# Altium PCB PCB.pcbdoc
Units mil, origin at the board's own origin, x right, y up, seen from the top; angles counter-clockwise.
Board outline 2605 x 3140 mil, 4 copper layers (Top Layer, Inner1, VCC, Bottom Layer); 72 components, 50 nets, 258 pads, 167 vias.
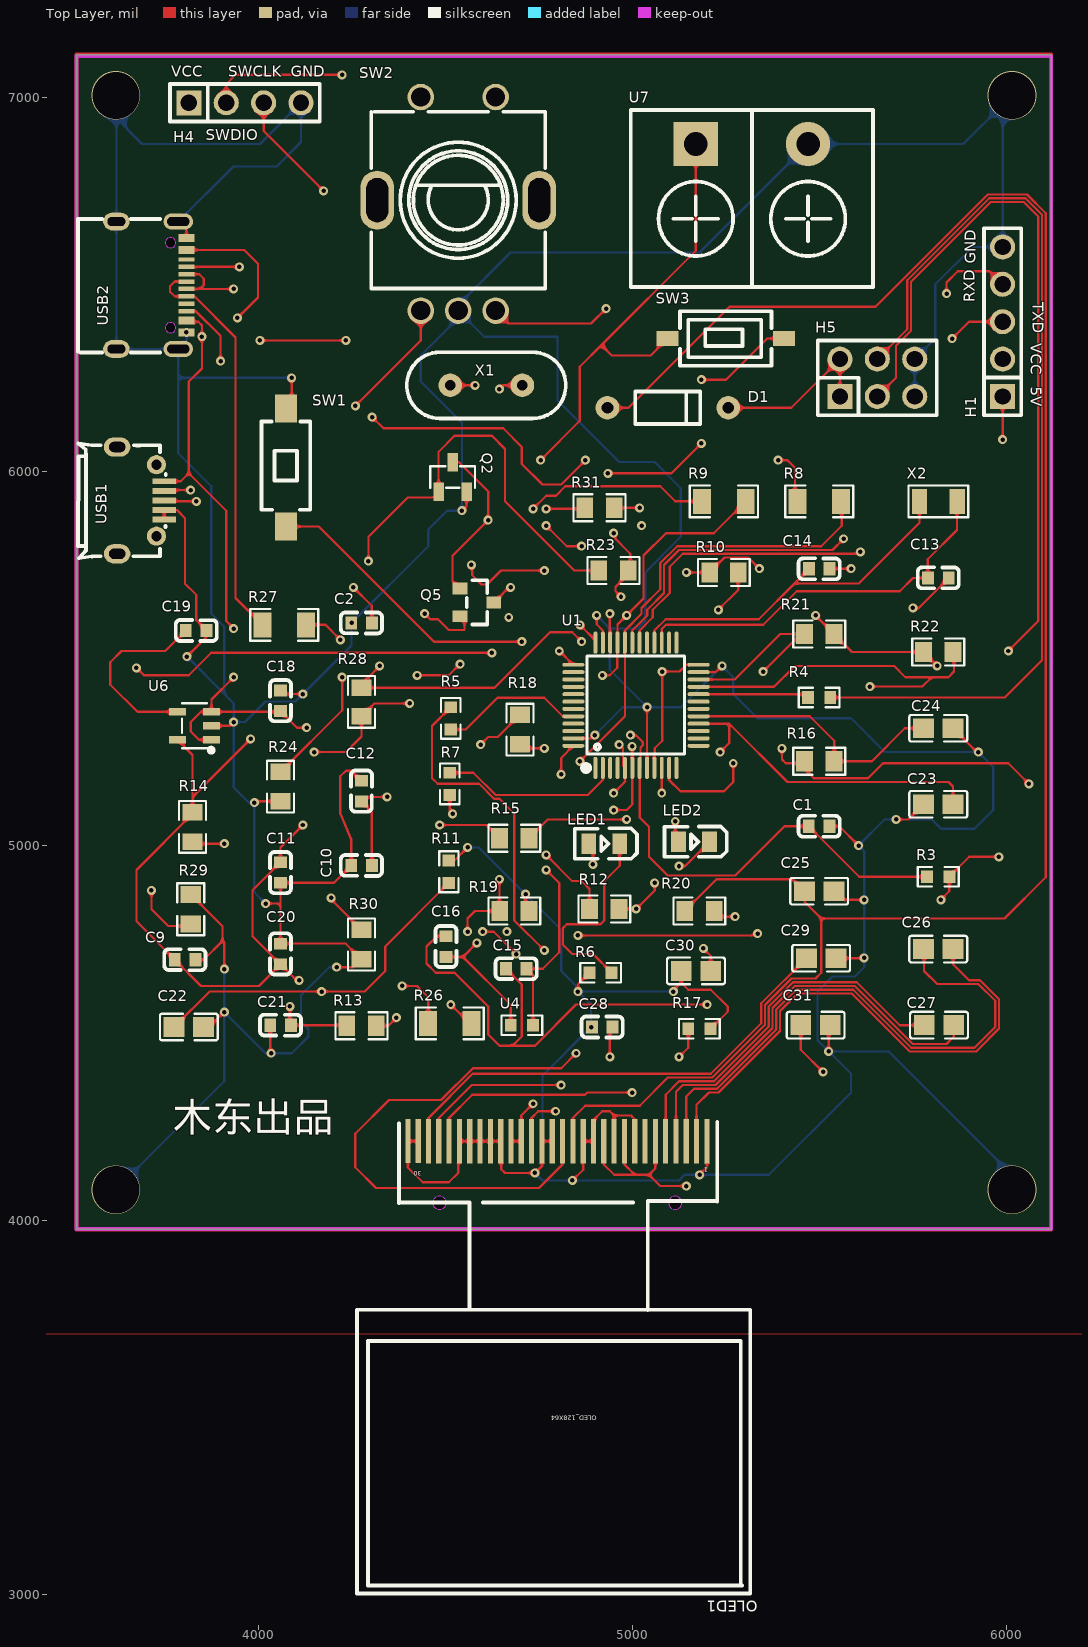
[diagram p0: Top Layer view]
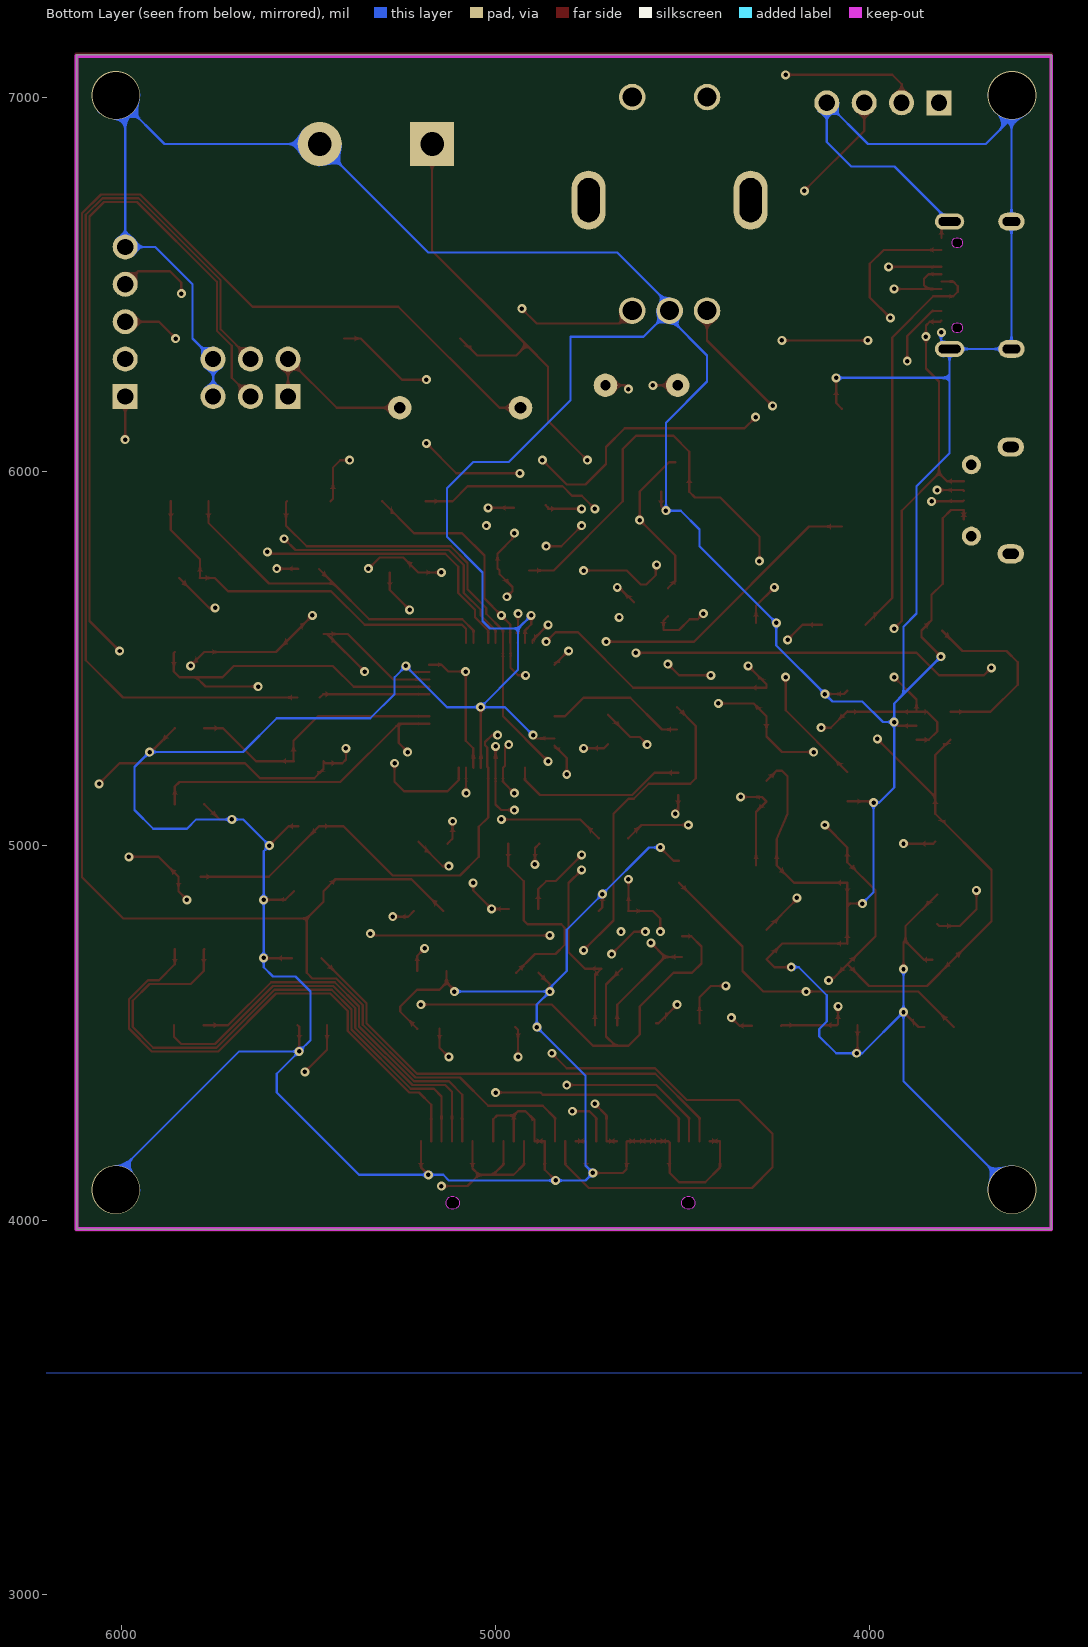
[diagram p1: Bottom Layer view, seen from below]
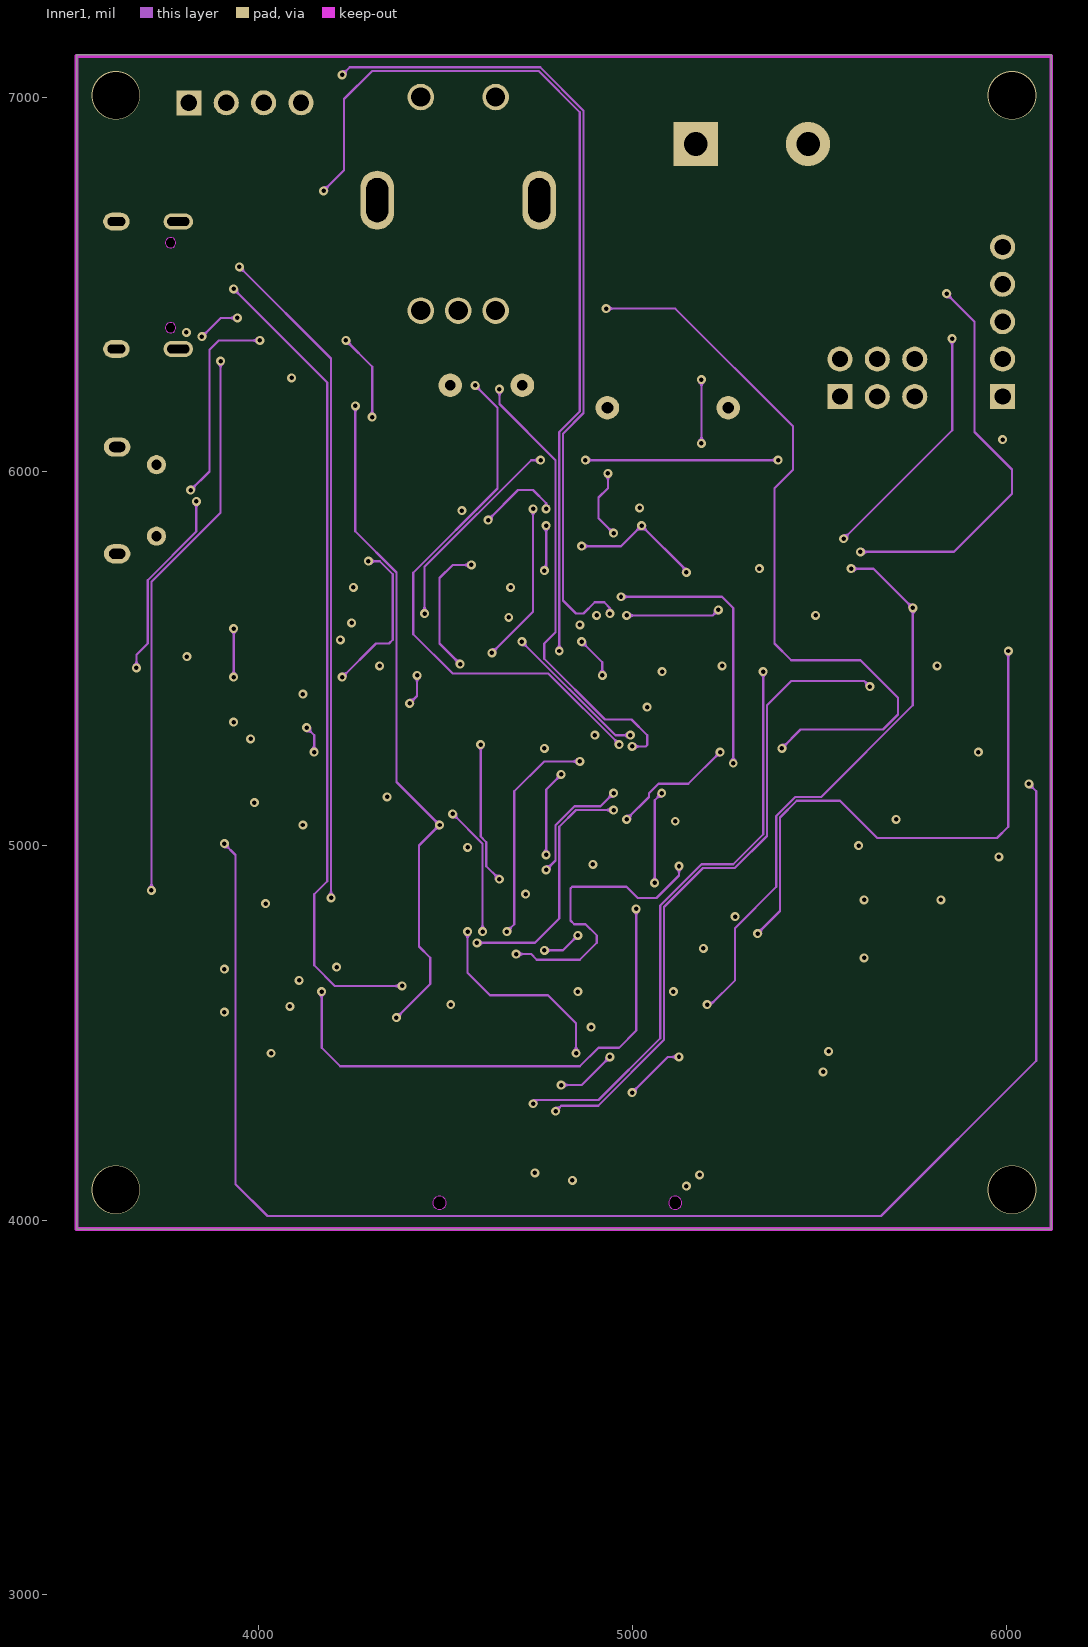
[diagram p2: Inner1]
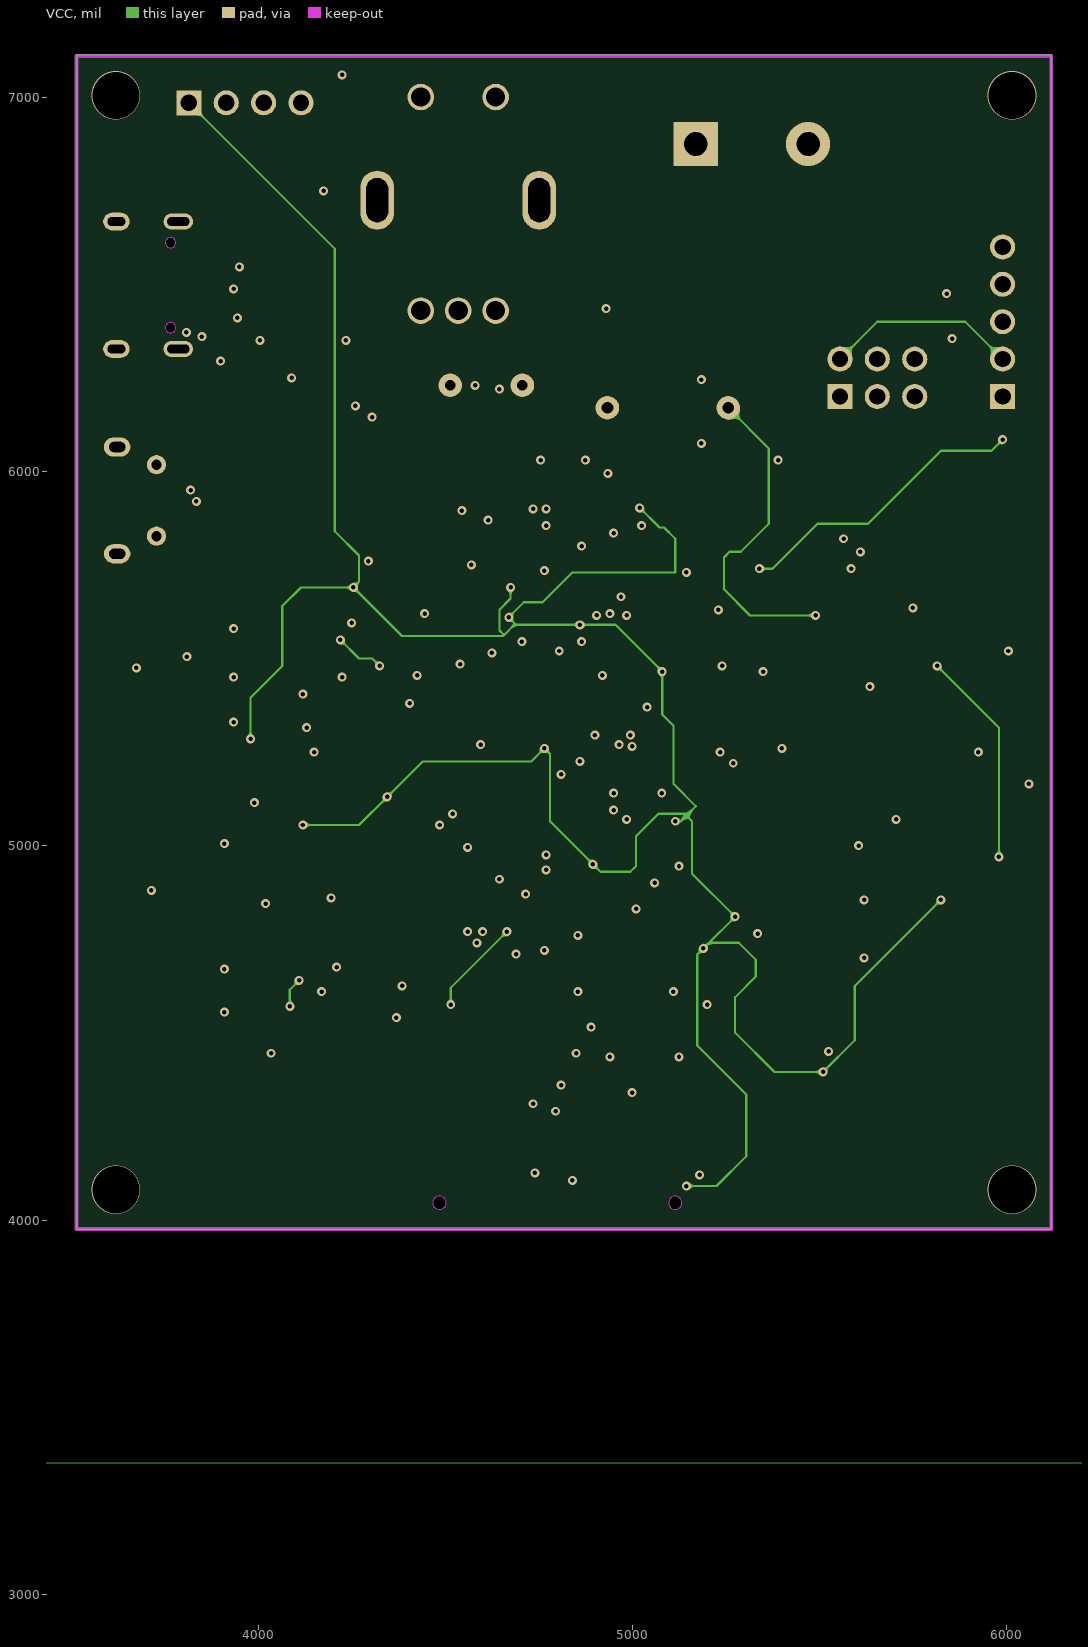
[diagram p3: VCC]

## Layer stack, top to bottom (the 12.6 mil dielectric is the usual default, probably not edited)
Top Solder Mask Layer: solder mask 0.4, Solder Resist, Dk 3.5
Top Layer: signal copper 1.4
Dielectric1: dielectric 12.6, FR-4, Dk 4.8
Inner1: signal copper 1.4
Dielectric2: dielectric 12.6, FR-4, Dk 4.8
VCC: signal copper 1.4
Dielectric3: dielectric 12.6, FR-4, Dk 4.8
Bottom Layer: signal copper 1.4
Bottom Solder Mask Layer: solder mask 0.4, Solder Resist, Dk 3.5

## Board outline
3515,3975 3515,7115 6120,7115 6120,3975

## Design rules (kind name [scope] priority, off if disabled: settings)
Clearance [All] p1: gap=10 ignorepadtopadclearanceinfootprint=FALSE except(0: Arc-Hole Track-Hole SMDPad-Hole THPad-Hole Via-Hole Fill-Hole Poly-Hole Region-Hole Text-Hole)
PolygonConnect [All] p1: connectstyle=Relief reliefconductorwidth=10 reliefentries=4 polygonreliefangle="90 Angle" airgapwidth=10
RoutingVias [All] p1: holewidth=28 width=50 viastyle="Through Hole" minholewidth=28 minwidth=50 maxholewidth=28 maxwidth=50
SolderMaskExpansion [All] p1: expansion=4 istentingtop=FALSE
Width [All] p1: maxlimit=10 minlimit=10 preferedwidth=10
30 further rules are at their usual default settings.

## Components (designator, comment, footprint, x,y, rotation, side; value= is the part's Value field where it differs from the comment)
C1 "0603B104K500NT" C0603 5499.37,5052.67 r180 top
C2 "0603B104K500NT" C0603 4276.64,5596.02 r0 top
C9 "0603B104K500NT" C0603 3805,4696.02 r0 top
C10 "0603B104K500NT" C0603 4276.64,4947.8 r0 top
C11 "0603B104K500NT" C0603 4060.11,4929.18 r90 top
C12 "0603B104K500NT" C0603 4276.23,5146.48 r270 top
C13 "0603CG200J500NT" C0603 5818.23,5716.38 r0 top
C14 "0603CG200J500NT" C0603 5499.98,5740.5 r0 top
C15 "0603CG200J500NT" C0603 4690.21,4672.01 r0 top
C16 "0603CG200J500NT" C0603 4502.2,4731.02 r270 top
C18 "CL10A105KB8NNNC" C0603 4059.89,5387.9 r270 top
C19 "0603B223K500NT" C0603 3834.59,5575.82 r180 top
C20 "0603B104K500NT" C0603 4059.89,4711.21 r270 top
C21 "CL10A106KP8NNNC" C0603 4060.3,4521.02 r0 top
C22 "0805B104K500NT" C0805 3815,4516.02 r180 top
C23 "0805B103K500NT_C52278" C0805 5817.92,5111.41 r0 top
C24 "0805B103K500NT_C52278" C0805 5817.92,5314.59 r0 top
C25 "GRM21BR61H106KE43L" C0805 5499.67,4879.06 r0 top
C26 "CL21B105KBFNNNE" C0805 5817.92,4724.2 r0 top
C27 "CL21B105KBFNNNE" C0805 5820,4521.02 r0 top
C28 "CL10A475KO8NNNC" C0603 4920,4516.02 r0 top
C29 "CL21A225KBQNNNE" C0805 5505,4700.04 r0 top
C30 "CL21B105KBFNNNE" C0805 5170.42,4666.08 r0 top
C31 "CL21B105KBFNNNE" C0805 5490,4521.02 r180 top
D1 "1N4148_C402212" DO-35_BD2.0-L4.2-P8.20-D0.5-RD 5095,6171.02 r180 top
H1 "PZ254V-11-05P" HDR-TH_5P-P2.54-V-M 5990,6401.02 r90 top
H4 "PZ254V-11-04P" HDR-TH_4P-P2.54-V-M 3965,6986.02 r0 top
H5 "PZ254V-12-6P" HDR-TH_6P-P2.54-V-M-R2-C3-S2.54 5655,6251.02 r0 top
LED1 "NCD0805R1" LED0805-R-RD 4925,5006.02 r180 top
LED2 "NCD0805R1" LED0805-R-RD 5165,5011.02 r180 top
OLED1 "N096-2864KSWEG01-H30" OLED_0.96-30P-P0.70-12864 4800,4211.02 r180 top
Q2 "SS8050_C2150" SOT-23-3_L2.9-W1.3-P1.90-LS2.4-BR 4520,5986.02 r270 top
Q5 "AO3400_C2938367" SOT-23_L2.9-W1.3-P1.90-LS2.4-BR 4585,5651.02 r180 top
R3 "0603WAF1002T5E" R0603 5817.92,4917.81 r0 top
R4 "RC0603FR-07100KL" R0603 5499.67,5396.59 r180 top
R5 "RC0603FR-07100KL" R0603 4515,5341.02 r90 top
R6 "0603WAF5100T5E" R0603 4915.42,4660.87 r180 top
R7 "0603WAF5100T5E" R0603 4512.31,5166.02 r90 top
R8 "1206W4F200JT5E" R1206 5499.67,5921.02 r0 top
R9 "1206W4F200JT5E" R1206 5245,5921.02 r0 top
R10 "0805W8F100JT5E" R0805_NEW 5245,5731.02 r0 top
R11 "NCP18XH103F03RB" R0603 4510,4931.02 r90 top
R12 "0805W8F1002T5E_C17414" R0805 4925.42,4831.65 r180 top
R13 "0805W8F1002T5E_C17414" R0805 4276.33,4519.49 r0 top
R14 "0805W8F1002T5E_C17414" R0805 3825,5051.02 r90 top
R15 "0805W8F1002T5E_C17414" R0805 4684.9,5020.55 r0 top
R16 "0805W8F1002T5E_C17414" R0805 5499.67,5226.6 r0 top
R17 "0603WAF9103T5E" R0603 5179.55,4511.45 r180 top
R18 "0805W8F4701T5E" R0805 4699.9,5311.02 r90 top
R19 "0805W8F4701T5E" R0805 4685,4826.02 r180 top
R20 "0805W8F4701T5E" R0805 5179.55,4826.02 r0 top
R21 "0805W8F4701T5E" R0805 5499.67,5566.57 r180 top
R22 "0805W8F4701T5E" R0805 5817.92,5518.3 r0 top
R23 "0805W8F1001T5E" R0805 4950,5736.02 r0 top
R24 "0805W8F1003T5E" R0805 4060,5158.54 r90 top
R26 "1206W4F200JT5E" R1206 4512.31,4526.02 r0 top
R27 "1206W4F200JT5E" R1206 4070,5591.02 r0 top
R28 "0805W8F100JT5E" R0805_NEW 4276.33,5384.94 r90 top
R29 "0805W8F5101T5E" R0805 3820,4831.02 r90 top
R30 "0805W8F5101T5E" R0805 4276.33,4736.72 r90 top
R31 "0805W8F1003T5E" R0805 4912.45,5903.66 r0 top
SW1 "TS-1101-C-W" SW-SMD_L6.0-W3.3-LS8.0 4075,6011.02 r270 top
SW2 "EC11E15244G1" SW-TH_EC11E15244G1 4535,6716.02 r0 top
SW3 "TS-1092S-B3D2-G" SW-SMD_L6.1-W3.6-LS7.9 5250,6356.02 r0 top
U1 "STM32F103C8T6" LQFP-48_L7.0-W7.0-P0.50-LS9.0-BL 5010,5376.02 r0 top
U4 "SC0603F1004F2BNRH" R0603 4705,4521.02 r0 top
U6 "RT9193-33GB" SOT-23-5_L3.0-W1.7-P0.95-LS2.8-BL 3830,5321.02 r90 top
U7 "KF7.62-2P" CONN-TH_KF7.62-2P 5320,6876.02 r0 top
USB1 "MicroXNJ" MICRO-USB-SMD_MICROXNJ 3686.26,5923.48 r270 top
USB2 "TYPE-C 16PIN 2MD(073)" USB-C-SMD_TYPE-C-6PIN-2MD-073 3715,6498.48 r270 top
X1 "X49SD8MSD2SC" OSC-TH_L10.0-W4.5-P5.00 4610,6231.02 r90 top
X2 "X321532768KGD2SI" OSC-SMD_L3.2-W1.5 5817.92,5921.04 r0 top

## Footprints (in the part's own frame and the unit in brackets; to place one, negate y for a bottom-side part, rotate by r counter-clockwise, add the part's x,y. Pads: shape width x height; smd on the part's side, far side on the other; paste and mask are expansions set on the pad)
C0603 [mm]
  rect 0.8x0.9 smd: 1(-0.7,0) 2(0.7,0)
  silkscreen extent -1.41,-0.71 1.39,0.72
C0805 [mm]
  rect 1.41x1.35 smd paste-100 mask+0.051: 1(-1,0) 2(1,0)
  silkscreen extent -1.96,-0.9 1.96,0.9
CONN-TH_KF7.62-2P [mm]
  rect 3x3 hole 1.6: 1(-3.81,0)
  round 3 hole 1.6: 2(3.81,0)
  silkscreen extent -8.22,-9.7 8.22,2.3
DO-35_BD2.0-L4.2-P8.20-D0.5-RD [mm]
  round 1.6 hole 0.8: 1(-4.1,0) 2(4.1,0)
  silkscreen extent -2.2,-1.1 2.2,1.1
HDR-TH_4P-P2.54-V-M [mm]
  rect 1.7x1.7 hole 1.1: 1(-3.81,0)
  round 1.7 hole 1.1: 2(-1.27,0) 3(1.27,0) 4(3.81,0)
  silkscreen extent -5.08,-1.27 5.08,1.27
HDR-TH_5P-P2.54-V-M [mm]
  rect 1.7x1.7 hole 1.1: 1(-5.08,0)
  round 1.7 hole 1.1: 2(-2.54,0) 3(0,0) 4(2.54,0) 5(5.08,0)
  silkscreen extent -6.35,-1.27 6.35,1.27
HDR-TH_6P-P2.54-V-M-R2-C3-S2.54 [mm]
  rect 1.7x1.7 hole 1.1: 1(-2.54,-1.27)
  round 1.7 hole 1.1: 2(-2.54,1.27) 3(0,-1.27) 4(0,1.27) 5(2.54,-1.27) 6(2.54,1.27)
  silkscreen extent -4.04,-2.54 4.04,2.54
LED0805-R-RD [mm]
  rect 1x1.4 smd: 1(1.05,0) 2(-1.05,0)
  silkscreen extent -2.22,-1.04 1.99,1.01
LQFP-48_L7.0-W7.0-P0.50-LS9.0-BL [mm]
  oval 0.27x1.5 smd paste+0 mask+0.05: 1(-2.75,-4.25) 2(-2.25,-4.25) 3(-1.75,-4.25) 4(-1.25,-4.25) 5(-0.75,-4.25) 6(-0.25,-4.25) 7(0.25,-4.25) 8(0.75,-4.25) 9(1.25,-4.25) 10(1.75,-4.25) 11(2.25,-4.25) 12(2.75,-4.25) 25(2.75,4.25) 26(2.25,4.25) 27(1.75,4.25) 28(1.25,4.25) 29(0.75,4.25) 30(0.25,4.25) 31(-0.25,4.25) 32(-0.75,4.25) 33(-1.25,4.25) 34(-1.75,4.25) 35(-2.25,4.25) 36(-2.75,4.25)
  oval 1.5x0.27 smd paste+0 mask+0.05: 13(4.25,-2.75) 14(4.25,-2.25) 15(4.25,-1.75) 16(4.25,-1.25) 17(4.25,-0.75) 18(4.25,-0.25) 19(4.25,0.25) 20(4.25,0.75) 21(4.25,1.25) 22(4.25,1.75) 23(4.25,2.25) 24(4.25,2.75) 37(-4.25,2.75) 38(-4.25,2.25) 39(-4.25,1.75) 40(-4.25,1.25) 41(-4.25,0.75) 42(-4.25,0.25) 43(-4.25,-0.25) 44(-4.25,-0.75) 45(-4.25,-1.25) 46(-4.25,-1.75) 47(-4.25,-2.25) 48(-4.25,-2.75)
  silkscreen extent -3.59,-4.46 3.3,3.34
MICRO-USB-SMD_MICROXNJ [mm]
  rect 0.4x1.6 smd paste-100 mask+0.051: 1(-1.3,1.596) 2(-0.65,1.596) 3(0,1.596) 4(0.65,1.596) 5(1.3,1.596)
  round 1.3 hole 0.7: 6(2.425,1.074) 9(-2.425,1.074)
  oval 1.3x1.8 hole 0.7 slot 1.1 at 90 deg: 7(3.625,-1.596) 8(-3.625,-1.596)
  silkscreen extent -3.87,-4.24 3.93,1.71
OLED_0.96-30P-P0.70-12864 [mm]
  rect 0.351x3 smd: 1(-10.15,0.002) 2(-9.45,0) 3(-8.75,0) 4(-8.05,0) 5(-7.35,0) 6(-6.65,0) 7(-5.95,0) 8(-5.25,0) 9(-4.55,0) 10(-3.85,0) 11(-3.15,0) 12(-2.45,0) 13(-1.75,0) 14(-1.05,0) 15(-0.35,0) 16(0.35,0) 17(1.05,0) 18(1.75,0) 19(2.45,0) 20(3.15,0) 21(3.85,0) 22(4.55,0) 23(5.25,0) 24(5.95,0) 25(6.65,0) 26(7.35,0) 27(8.05,0) 28(8.75,-0.001) 29(9.45,-0.002) 30(10.15,-0.002)
  Board Outline Layer board cut-out: -8.45,4.18 -8.45,4.091 -8.381,3.925 -8.255,3.799 -8.089,3.73 -7.91,3.73 -7.745,3.799 -7.618,3.925 -7.55,4.091 -7.55,4.18 -7.55,4.27 -7.618,4.435 -7.745,4.562 -7.91,4.63 -8.089,4.63 -8.255,4.562 -8.381,4.435 -8.45,4.27 -8.45,4.18
  Board Outline Layer board cut-out: 7.55,4.18 7.55,4.091 7.618,3.925 7.745,3.799 7.911,3.73 8.09,3.73 8.255,3.799 8.382,3.925 8.45,4.091 8.45,4.18 8.45,4.27 8.382,4.435 8.255,4.562 8.09,4.63 7.91,4.63 7.745,4.562 7.618,4.435 7.55,4.27 7.55,4.18
  Multi-Layer keep-out region: -8.45,4.18 -8.45,4.091 -8.381,3.925 -8.255,3.799 -8.089,3.73 -7.91,3.73 -7.745,3.799 -7.618,3.925 -7.55,4.091 -7.55,4.18 -7.55,4.27 -7.618,4.435 -7.745,4.562 -7.91,4.63 -8.089,4.63 -8.255,4.562 -8.381,4.435 -8.45,4.27 -8.45,4.18
  Multi-Layer keep-out region: 7.55,4.18 7.55,4.091 7.618,3.925 7.745,3.799 7.911,3.73 8.09,3.73 8.255,3.799 8.382,3.925 8.45,4.091 8.45,4.18 8.45,4.27 8.382,4.435 8.255,4.562 8.09,4.63 7.91,4.63 7.745,4.562 7.618,4.435 7.55,4.27 7.55,4.18
  silkscreen extent -13.1,-1.3 13.6,30.7
OSC-SMD_L3.2-W1.5 [mm]
  rect 1.05x1.7 smd: 1(-1.275,0) 2(1.275,0)
  silkscreen extent -2.03,-1.08 2.03,1.08
OSC-TH_L10.0-W4.5-P5.00 [mm]
  round 1.6 hole 0.7: 1(0,2.45) 2(0,-2.45)
  silkscreen extent -2.25,-5.39 2.25,5.39
R0603 [mil]
  rect 31.75x34.02 smd paste-3937.01 mask+2: 1(-29.66,0) 2(29.66,0)
  silkscreen extent -55,-26 55,26
R0805 [mm]
  rect 1.133x1.377 smd paste-100 mask+0.051: 1(-1,0) 2(1,0)
  silkscreen extent -1.76,-0.92 1.76,0.92
R0805_NEW [mil]
  rect 44.59x54.21 smd paste-3937.01 mask+2: 1(-38.04,0) 2(38.04,0)
  silkscreen extent -69,-36 69,36
R1206 [mil]
  rect 47.54x66.97 smd paste-3937.01 mask+2: 1(-58.22,0) 2(58.22,0)
  silkscreen extent -91,-42 91,42
SOT-23-3_L2.9-W1.3-P1.90-LS2.4-BR [mm]
  rect 1.25x0.7 smd: 1(1,-0.95) 2(1,0.95) 3(-1,0)
  silkscreen extent -0.73,-1.53 0.73,1.53
SOT-23-5_L3.0-W1.7-P0.95-LS2.8-BL [mm]
  rect 0.49x1.157 smd: 1(-0.95,-1.154) 2(0,-1.154) 3(0.95,-1.154)
  rect 0.49x1.175 smd: 4(0.95,1.154) 5(-0.95,1.154)
  silkscreen extent -1.8,-1.29 1.53,0.85
SOT-23_L2.9-W1.3-P1.90-LS2.4-BR [mm]
  rect 1x0.8 smd: 1(1.15,-0.95) 2(1.15,0.95) 3(-1.15,0)
  silkscreen extent -0.7,-1.5 0.7,1.5
SW-SMD_L6.0-W3.3-LS8.0 [mm]
  rect 1.9x1.5 smd: 1(-4,0) 2(4,0)
  silkscreen extent -3.14,-1.67 2.86,1.63
SW-SMD_L6.1-W3.6-LS7.9 [mm]
  rect 1.5x1 smd: 1(-3.95,0) 2(3.95,0)
  silkscreen extent -3.1,-1.85 3.1,1.85
SW-TH_EC11E15244G1 [mm]
  oval 2.3x4 hole 1.5 slot 3 at 90 deg: 6(5.5,0.25) 7(-5.5,0.25)
  round 1.8 hole 1.3: A(-2.54,-7.25) B(2.54,-7.25) C(0,-7.25) D(-2.54,7.25) E(2.54,7.25)
  silkscreen extent -5.9,-5.75 5.9,6.25
USB-C-SMD_TYPE-C-6PIN-2MD-073 [mm]
  rect 0.55x1.1 smd paste-100 mask+0.05: 1(-3.2,2.375) 2(-2.4,2.375) 11(2.4,2.375) 12(3.2,2.375)
  rect 0.3x1.1 smd paste-100 mask+0.05: 3(-1.75,2.375) 4(-1.25,2.375) 5(-0.75,2.375) 6(-0.25,2.375) 7(0.25,2.375) 8(0.75,2.375) 9(1.25,2.375) 10(1.75,2.375)
  oval 1.1x2 hole 0.6 slot 1.5 at 90 deg paste+0 mask+0.05: 13(-4.325,1.825) 14(4.325,1.825)
  oval 1.2x1.8 hole 0.6 slot 1.2 at 90 deg paste+0 mask+0.05: 13(-4.325,-2.375) 14(4.325,-2.375)
  Board Outline Layer board cut-out: -2.89,1.655 -2.96,1.655 -3.088,1.602 -3.187,1.503 -3.24,1.375 -3.24,1.235 -3.187,1.107 -3.088,1.008 -2.959,0.955 -2.89,0.955 -2.82,0.955 -2.692,1.008 -2.593,1.107 -2.54,1.235 -2.54,1.375 -2.593,1.503 -2.692,1.602 -2.82,1.655 -2.89,1.655
  Board Outline Layer board cut-out: 2.89,1.655 2.821,1.655 2.692,1.602 2.593,1.503 2.54,1.375 2.54,1.235 2.593,1.107 2.692,1.008 2.821,0.955 2.89,0.955 2.96,0.955 3.088,1.008 3.187,1.107 3.24,1.235 3.24,1.375 3.187,1.503 3.088,1.602 2.96,1.655 2.89,1.655
  Multi-Layer keep-out region: -2.89,1.655 -2.96,1.655 -3.088,1.602 -3.187,1.503 -3.24,1.375 -3.24,1.235 -3.187,1.107 -3.088,1.008 -2.959,0.955 -2.89,0.955 -2.82,0.955 -2.692,1.008 -2.593,1.107 -2.54,1.235 -2.54,1.375 -2.593,1.503 -2.692,1.602 -2.82,1.655 -2.89,1.655
  Multi-Layer keep-out region: 2.89,1.655 2.821,1.655 2.692,1.602 2.593,1.503 2.54,1.375 2.54,1.235 2.593,1.107 2.692,1.008 2.821,0.955 2.89,0.955 2.96,0.955 3.088,1.008 3.187,1.107 3.24,1.235 3.24,1.375 3.187,1.503 3.088,1.602 2.96,1.655 2.89,1.655
  silkscreen extent -4.5,-4.97 4.57,0.6

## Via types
v1: diameter 24, hole 12, Top Layer to Bottom Layer, 163 vias
v2: diameter 130, hole 126, Top Layer to Bottom Layer, 4 vias

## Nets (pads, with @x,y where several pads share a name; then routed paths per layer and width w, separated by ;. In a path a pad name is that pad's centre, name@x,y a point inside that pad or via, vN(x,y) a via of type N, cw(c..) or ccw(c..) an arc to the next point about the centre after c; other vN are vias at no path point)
$1N1632: H5.3 R5.2 | length 4926.9
  Top Layer w6: R5.2 4465,5320.68 4465,5181.02 4480,5166.02 4590.84,5166.02 4630.85,5126.01 4645.02,5126.01 4685,5086.02 4685,4801.02 v1(4765,4721.02) ; v1(4855,4761.02) 5330,4761.02 v1(5335,4766.02) ; H5.3 5705,6251.02 5705,6336.86 5745.02,6376.87 5745.02,6507.71 5958.3,6720.99 6046.7,6720.99 6085.16,6682.53 6085.16,5601.18 v1(6005,5521.02)
  Inner1 w6: v1(4765,4721.02) 4815,4721.02 v1(4855,4761.02) ; v1(5335,4766.02) 5395,4826.02 5395,5076.02 5440,5121.02 5555,5121.02 5655,5021.02 5975,5021.02 6005,5051.02 v1(6005,5521.02)
$1N1633: H5.4 R4.1 | length 2511
  Top Layer w6: R4.1 5995.74,5396.59 6095.17,5496.02 6095.17,6686.68 6050.85,6731.01 5954.15,6731.01 5735,6511.86 5735,6381.02 H5.4
$1N1645: LED1.2 R6.1 | length 546.6
  Top Layer w6: R6.1 4894.93,4711.02 4840,4711.02 4815.02,4736.01 4815.02,4781.04 4825,4791.02 4915,4791.02 4925,4801.02 4925,4906.02 4966.35,4947.37 LED1.2
$1N1649: LED2.2 R7.1 | length 1410.6
  Top Layer w6: R7.1 4512.31,5093.71 v1(4520,5086.02) ; v1(4600,4771.02) 4630,4771.02 v1(4690,4711.02) ; v1(5125,4946.02) 5141.35,4946.02 LED2.2
  Inner1 w6: v1(4520,5086.02) 4600,5006.02 v1(4600,4771.02) ; v1(4690,4711.02) 4730,4711.02 4745,4696.02 4860,4696.02 4905,4741.02 4905,4761.02 4875,4791.02 4845,4791.02 4835,4801.02 4835,4886.02 4840,4891.02 4985,4891.02 5015,4861.02 5065,4861.02 5125,4921.02 v1(5125,4946.02)
$1N1662: R8.1 USB1.2 | length 2435.6
  Top Layer w6: USB1.2 3751.07,5951.02 v1(3820,5951.02) ; v1(4005,6351.02) v1(4235,6351.02) ; v1(4305,6146.02) 4335,6116.02 4655,6116.02 4705,6066.02 4705,6021.02 4760,5966.02 4810,5966.02 v1(4875,6031.02) ; v1(5390,6031.02) 5415,6031.02 5435,6011.02 5435,5927.47 R8.1
  Inner1 w6: v1(3820,5951.02) 3870,6001.02 3870,6326.02 3895,6351.02 v1(4005,6351.02) ; v1(4235,6351.02) 4305,6281.02 v1(4305,6146.02) ; v1(4875,6031.02) v1(5390,6031.02)
$1N1663: R9.1 USB1.3 | length 2505.1
  Top Layer w6: v1(3675,5476.02) 3695,5456.02 3815,5456.02 3875,5516.02 v1(4625,5516.02) ; USB1.3 3751.56,5921.02 v1(3835,5921.02) ; v1(4735,5901.02) 4770,5936.02 4796,5936.02 4821,5961.02 5075,5961.02 5115,5921.02 R9.1
  Inner1 w6: v1(3675,5476.02) 3675,5511.04 3704.98,5541.02 3704.98,5710.17 3835,5840.19 v1(3835,5921.02) ; v1(4625,5516.02) 4735,5626.02 v1(4735,5901.02)
$1N1675: C13.2 C14.2 C15.1 C16.1 | length 3002.6
  Top Layer w6: C16.1 4477.56,4758.58 4450,4731.02 4450,4686.02 4475,4661.02 4525,4661.02 4615,4571.02 4615,4496.02 4645,4466.02 4680,4466.02 ; C15.1 4705,4629.66 4705,4491.02 4680,4466.02 ; v1(5200,4576.02) 4850,4576.02 4740,4466.02 4680,4466.02 ; C14.2 5528.06,5741.02 v1(5585,5741.02) ; v1(5750,5636.02) 5765.43,5636.02 C13.2
  Inner1 w6: v1(5200,4576.02) 5210,4576.02 5275,4641.02 5275,4781.04 5384.98,4891.02 5384.98,5080.17 5435.85,5131.04 5505.02,5131.04 5750,5376.02 v1(5750,5636.02) 5645,5741.02 v1(5585,5741.02)
$1N1700: C19.2 U6.4 | length 506.8
  Top Layer w6: U6.4 3677.6,5358.42 3605,5431.02 3605,5491.02 3635,5521.02 3752.23,5521.02 C19.2
$1N6862: R13.2 R15.1 SW2.A | length 2366.2
  Top Layer w6: v1(4260,6176.02) 4434.99,6351.02 SW2.A ; R13.2 4348.47,4519.49 v1(4370,4541.02) ; v1(4485,5056.02) 4610.06,5056.02 R15.1
  Inner1 w6: v1(4260,6176.02) 4260,5841.02 4370,5731.02 4370,5171.02 v1(4485,5056.02) 4430,5001.02 4430,4731.02 4460,4701.02 4460,4631.02 v1(4370,4541.02)
$1N6871: R14.1 R16.1 SW2.B | length 7211.5
  Top Layer w6: R14.1 3830.63,5006.02 v1(3910,5006.02) ; SW2.B 4669.56,6396.02 4890,6396.02 v1(4930,6436.02) ; v1(5400,5261.02) 5400,5231.02 5410,5221.02 5454.72,5221.02 R16.1 5460.3,5205.74 5485,5181.04 5630.02,5181.04 5670,5221.02 6005,5221.02 v1(6060,5166.02)
  Inner1 w6: v1(3910,5006.02) 3940,4976.02 3940,4096.02 4025,4011.02 5665,4011.02 6080,4426.02 6080,5146.02 v1(6060,5166.02) ; v1(4930,6436.02) 5115,6436.02 5430,6121.02 5430,6006.02 5380,5956.02 5380,5541.02 5425,5496.02 5610,5496.02 5710,5396.02 5710,5351.02 5670,5311.02 5450,5311.02 v1(5400,5261.02)
$1N7228: OLED1.26 R17.2 | length 829.7
  Top Layer w6: OLED1.26 4510.63,4273.07 4572.59,4335.02 4874,4335.02 4880,4341.02 v1(5000,4341.02) ; v1(5125,4436.02) 5149.89,4460.91 R17.2
  Inner1 w6: v1(5000,4341.02) 5095,4436.02 v1(5125,4436.02)
$1N7293: OLED1.15 R18.2 R19.2 | length 2695.2
  Top Layer w6: v1(4560,4771.02) 4560,4806.02 4580,4826.02 R19.2 4645,4826.65 v1(4645,4911.02) ; v1(4595,5271.02) 4615,5291.02 4640.53,5291.02 R18.2 ; OLED1.15 4813.78,4148.96 4750.85,4086.02 4315,4086.02 4260,4141.02 4260,4231.02 4350,4321.02 4489.24,4321.02 4574.24,4406.02 4810,4406.02 v1(4850,4446.02)
  Inner1 w6: v1(4560,4771.02) 4560,4661.02 4620,4601.02 4775,4601.02 4850,4526.02 v1(4850,4446.02) ; v1(4595,5271.02) 4595,5025.19 4610.02,5010.17 4610.02,4946.02 v1@4640,4916.04
$1N7764: C25.1 D1.2 OLED1.14 R20.1 | length 5371.9
  Top Layer w6: OLED1.14 4841.34,4273.07 4874.3,4306.02 5020,4306.02 5094.98,4381.01 5214.15,4381.01 5355.02,4521.87 5355.02,4575.26 5425.77,4646.02 5490,4646.02 5505,4661.02 5505,4806.02 ; D1.2 4990,6171.02 5260,6441.02 5650,6441.02 5950,6741.02 6055,6741.02 6105.19,6690.83 6105.19,4916.02 5995.19,4806.02 5505,4806.02 ; R20.1 5225.16,4911.01 5428.36,4911.01 C25.1 5460.3,4850.72 5505,4806.02
$1N8175: C26.1 OLED1.3 | length 1533.4
  Top Layer w6: OLED1.3 5144.49,4330.51 5164.94,4350.96 5226.59,4350.96 5385.06,4509.43 5385.06,4562.82 5438.22,4615.97 5590.88,4615.97 5745.85,4461.01 5914.98,4461.01 5970,4516.02 5970,4586.02 5925,4631.02 5815,4631.02 5780,4666.02 5780,4722.75 C26.1
$1N8179: C26.2 OLED1.2 | length 1429.3
  Top Layer w6: OLED1.2 5172.05,4308.07 5204.92,4340.94 5230.74,4340.94 5395.08,4505.28 5395.08,4558.67 5442.37,4605.96 5586.73,4605.96 5741.7,4450.99 5919.13,4450.99 5980.02,4511.87 5980.02,4590.17 5929.15,4641.04 5900,4641.04 5857.29,4683.75 C26.2
$1N8184: C27.2 OLED1.4 | length 1125.7
  Top Layer w6: OLED1.4 5116.93,4342.95 5134.95,4360.97 ; 5135,4360.97 5222.45,4360.97 5375.05,4513.58 5375.05,4566.97 5434.07,4625.99 5595.03,4625.99 5750,4471.02 5840,4471.02 5859.37,4490.39 C27.2
$1N8191: C27.1 OLED1.5 | length 1019.1
  Top Layer w6: OLED1.5 5089.37,4335.39 5124.97,4370.99 5218.3,4370.99 5365.03,4517.72 5365.03,4571.11 5429.92,4636.01 5600.02,4636.01 5715,4521.02 C27.1
$1N8376: C28.2 OLED1.27 | length 669.6
  Top Layer w6: OLED1.27 4483.07,4273.07 4571.02,4361.02 v1(4810,4361.02) ; v1(4940,4436.02) 4940,4508.46 C28.2
  Inner1 w6: v1(4810,4361.02) 4865,4361.02 v1(4940,4436.02)
$1N8381: C29.1 OLED1.28 | length 1280.3
  Top Layer w6: OLED1.28 4455.51,4273.13 4573.4,4391.02 5210,4391.02 5345,4526.02 5345,4579.41 C29.1
$1N9584: Q2.1 R23.1 R24.2 | length 1838.6
  Top Layer w6: R24.2 4225,5362.91 v1(4225,5451.02) ; v1(4295,5761.02) 4295,5826.02 4400,5931.02 4466.97,5931.02 Q2.1 4482.6,6053.62 4525,6096.02 4625,6096.02 4660,6061.02 4660,5921.02 4845,5736.02 R23.1
  Inner1 w6: v1(4225,5451.02) 4315,5541.02 4350,5541.02 4359.98,5551.01 4359.98,5726.02 4324.98,5761.02 v1(4295,5761.02)
$1N10286: R27.1 USB2.6 USB2.8 | length 1086.9
  Top Layer w6: USB2.6 3777.3,6508.32 3765,6496.02 3765,6481.02 3777.07,6468.95 USB2.8 3830.22,6468.95 3940,6359.17 3940,5662.8 R27.1
$1N10301: R26.1 USB2.5 USB2.7 | length 2545.7
  Top Layer w6: USB2.7 3845,6488.63 ; USB2.5 3843.02,6528 3855,6516.02 3855,6498.63 3845,6488.63 ; v1(3935,6488.63) 3845,6488.63 ; v1(4385,4626.02) 4425,4626.02 4455,4596.02 4455,4526.93 R26.1
  Inner1 w6: v1(3935,6488.63) 4184.98,6238.65 4184.98,4906.01 4150,4871.02 4150,4681.02 4205,4626.02 v1(4385,4626.02)
$1N10500: R29.1 USB2.10 | length 1853.5
  Top Layer w6: v1(3715,4881.02) 3715,4831.02 3760,4786.02 3814.37,4786.02 R29.1 ; USB2.10 3833.16,6429.57 3900,6362.73 v1(3900,6296.02)
  Inner1 w6: v1(3715,4881.02) 3715,5706.02 3900,5891.02 v1(3900,6296.02)
$1N10523: R30.2 USB2.4 | length 2048.3
  Top Layer w6: USB2.4 v1(3950,6547.68) ; v1(4195,4861.02) 4195,4857.42 R30.2
  Inner1 w6: v1(3950,6547.68) 4195,6302.68 v1(4195,4861.02)
$1N12991: Q5.2 SW3.1 U7.1 | length 1943.5
  Top Layer w6: v1(4445,5621.02) 4460,5606.02 4480.94,5606.02 4510,5576.96 4551.62,5576.96 4551.62,5601.72 Q5.2 ; v1(4755,6031.02) 4860,6136.02 4860,6281.02 4917.66,6338.68 ; SW3.1 5049.49,6311.02 4945,6311.02 4917.66,6338.36 4917.66,6338.68 ; U7.1 5170,6591.02 4917.66,6338.68
  Inner1 w6: v1(4445,5621.02) 4445,5746.02 4730,6031.02 v1(4755,6031.02)
$1N13700: Q2.3 Q5.1 R31.1 | length 753.5
  Top Layer w6: Q2.3 4536.78,6025.39 4615,5947.17 v1(4615,5871.02) 4520,5776.02 4520,5708.15 Q5.1 ; v1(4770,5901.02) 4859.99,5901.02 4859.98,5904.73 R31.1@4866,5910.74
  Inner1 w6: v1(4615,5871.02) 4695,5951.02 4735,5951.02 4770,5916.02 v1(4770,5901.02)
+5V: C18.2 H1.1 R10.1 R28.1 U6.1 U6.3 USB1.1 USB2.2 USB2.11 | length 5116.5
  Top Layer w6: USB1.1 3793.63,5974.66 3815,5996.02 ; USB2.11 3811.46,6401.02 3840,6401.02 3850,6391.02 v1(3850,6361.02) 3850,6276.02 3815,6241.02 3815,5996.02 ; USB2.2 3963.06,6592.96 4000,6556.02 4000,6466.02 v1(3945,6411.02) ; U6.1 3842.4,5283.62 3820,5306.02 3820,5331.02 3847.4,5358.42 U6.3 ; v1(3935,5451.02) 3875.42,5391.44 U6.3 ; v1(3935,5581.02) 3915,5601.02 3915,5896.02 3815,5996.02 ; v1(4130,5316.02) 4104.22,5316.02 C18.2 4057.97,5358.42 U6.3 ; v1(4150,5251.02) 4235,5251.02 4276.33,5292.35 R28.1 4310.45,5381.02 v1(4405,5381.02) ; v1(4425,5456.02) 4510,5456.02 v1(4540,5486.02) ; v1(4570,5751.02) 4572.22,5748.81 4572.22,5723.81 4597.22,5698.81 4612.13,5698.81 4649.35,5736.02 v1(4765,5736.02) ; v1(4770,5856.02) 4825,5801.02 v1(4865,5801.02) ; v1(5145,5731.02) R10.1 5246.91,5770.97 5310,5770.97 ; 5310.05,5770.97 v1(5340,5741.02) ; v1(5990,6086.02) H1.1
  Inner1 w6: v1(3850,6361.02) 3900,6411.02 v1(3945,6411.02) ; v1(3935,5451.02) v1(3935,5581.02) ; v1(4130,5316.02) 4150,5296.02 v1(4150,5251.02) ; v1(4405,5381.02) 4425,5401.02 v1(4425,5456.02) ; v1(4540,5486.02) 4485,5541.02 4485,5716.02 4520,5751.02 v1(4570,5751.02) ; v1(4765,5736.02) 4770,5741.02 v1(4770,5856.02) ; v1(4865,5801.02) 4970,5801.02 v1(5025,5856.02) 5145,5736.02 v1(5145,5731.02)
  VCC w6: v1(5340,5741.02) 5375,5741.02 5495,5861.02 5630,5861.02 5825,6056.02 5960,6056.02 v1(5990,6086.02)
ADC: C22.2 R11.1 R12.1 U1.10 | length 2759.4
  Top Layer w6: C22.2 3870.63,4611.02 v1(4170,4611.02) 4285,4611.02 4340,4666.02 4340,4731.36 R11.1 ; R12.1 v1(5010.63,4831.65) 5060,4881.02 v1(5060,4901.02) ; v1(5078.9,5141.02) U1.10
  Inner1 w6: v1(4170,4611.02) 4170,4461.02 4220,4411.02 4860,4411.02 4910,4461.02 4965,4461.02 5010.63,4506.65 v1(5010.63,4831.65) ; v1(5060,4901.02) 5060,5122.12 v1(5078.9,5141.02)
BOOT0: R5.1 U1.44 | length 383.3
  Top Layer w6: R5.1 4555.34,5311.36 4640,5396.02 4765,5396.02 4814.53,5346.49 U1.44
BOOT1: R4.2 U1.20 | length 296.4
  Top Layer w6: U1.20 5461.05,5405.55 R4.2
EC_A: C23.2 R15.2 U1.16 | length 1494.8
  Top Layer w6: R15.2 4774.74,5071.02 v1(4985,5071.02) ; U1.16 5259.21,5326.81 ; v1(5235,5251.02) 5259.21,5275.23 5259.21,5326.81 ; C23.2 5857.29,5158.73 5845,5171.02 5415,5171.02 5259.21,5326.81
  Inner1 w6: v1(4985,5071.02) 5045,5131.02 5045,5141.02 5070,5166.02 5150,5166.02 v1(5235,5251.02)
EC_B: C24.1 R16.2 U1.17 | length 720.6
  Top Layer w6: U1.17 5474.53,5346.49 5540,5281.02 5540,5227.56 R16.2 5640.58,5226.6 5728.57,5314.59 C24.1
GND: C1.1 C2.1 C9.2 C10.1 C11.1 C12.1 C18.1 C19.1 C20.1 C21.1 C22.1 C23.1 C24.2 C25.2 C28.1 C29.2 C30.1 C31.1 H1.5 H4.4 H5.5 H5.6 OLED1.1 OLED1.8 OLED1.10 OLED1.12 OLED1.13 OLED1.16 OLED1.17 OLED1.21 OLED1.22 OLED1.23 OLED1.24 OLED1.25 OLED1.29 OLED1.30 Q2.2 R6.2 R11.2 R17.1 R19.1 R24.1 R29.2 R30.1 SW1.1 SW2.C U1.8 U1.23 U1.35 U1.47 U6.2 U7.2 USB1.4 USB1.5 USB2.1 USB2.12 USB2.13 USB2.14 | length 21780.5
  Top Layer w6: USB1.5 USB1.4 3783.14,5897.89 3805,5876.02 3805,5701.02 3835,5671.02 3835,5602.97 C19.1 3862.15,5558.17 v1(3810,5506.02) ; USB2.13@3786.85,6668.75 3808.5,6647.1 USB2.1 ; R29.2 3905,4785.39 3905,4746.02 ; C9.2 3855,4696.02 3905,4746.02 ; C22.1 3870,4516.02 v1(3910,4556.02) ; U6.2 3925,5321.02 v1(3935,5331.02) ; v1(3910,4671.02) 3910,4741.02 3905,4746.02 ; v1(3990,5116.02) 3993.15,5119.17 R24.1 ; v1(4020,4846.02) 4057.83,4846.02 4060.11,4848.3 ; C21.1 4032.74,4448.28 v1(4035,4446.02) ; C20.1 C20.1@4060.11,4738.99 ; C18.1 4069.34,5406.02 v1(4120,5406.02) ; SW1.1 4090,6183.5 v1(4090,6251.02) ; v1(4210,4676.02) 4255,4676.02 R30.1 4234.7,4738.99 C20.1@4060.11,4738.99 ; C12.1 4249.25,5201.02 4235,5201.02 4220,5186.02 4220,5086.02 4249.08,5016.94 C10.1 4202.9,4901.62 C11.1 4060.11,4848.3 ; OLED1.29 OLED1.30 4400.39,4140.63 4440,4101.02 4510,4101.02 4535,4126.02 4535,4207.82 OLED1.25 OLED1.24 OLED1.23 OLED1.22 OLED1.21 4650,4209.43 4650,4136.02 4660,4126.02 v1(4740,4126.02) 4758.66,4144.68 OLED1.17 OLED1.16 ; R11.2 4524.66,4960.68 v1(4560,4996.02) ; v1(4545,5896.02) 4557.4,5908.42 Q2.2 ; v1(4715,4871.02) 4715,4835.39 R19.1 ; v1(4840,4106.02) 4868.9,4134.92 OLED1.13 OLED1.12 4896.46,4267.48 4920,4291.02 4940,4291.02 4951.57,4279.45 ; U1.47 4891.42,5287.44 v1(4900,5296.02) ; v1(4855,4611.02) 4855,4630.1 R6.2 ; v1(4890,4516.02) C28.1 ; v1(4905,5616.02) 4905,5592.29 4921.42,5575.87 U1.35 ; OLED1.10 4951.57,4279.45 ; OLED1.8 5006.69,4269.33 4996.57,4279.45 4951.57,4279.45 ; U1.8 5039.53,5370.55 v1(5040,5371.02) ; v1(5110,4611.02) 5110,4613.92 5131.05,4634.97 ; C30.1 5131.05,4634.97 ; U1.23 5223.58,5464.6 v1(5240,5481.02) ; v1(5180,4121.02) 5199.61,4140.63 OLED1.1 ; R17.1 5255,4557.24 5255,4571.02 5210,4616.02 5150,4616.02 5131.05,4634.97 ; v1(5525,4451.02) 5525,4516.65 C31.1 ; C1.1 5553.35,5052.67 v1(5605,5001.02) ; C25.2 5562.08,4856.02 v1(5620,4856.02) ; C29.2 5619.02,4700.04 v1(5620,4701.02) ; v1(5705,5071.02) 5738.16,5071.02 C23.1 ; C24.2 5920.86,5251.02 v1(5925,5251.02) ; C20.1@4060.11,4738.99 4060.11,4848.3
  Bottom Layer w6: v2(3620,4081.02) 3910,4371.02 v1(3910,4556.02) ; v2(3620,7006.02) 3621.49,7004.53 v2@3621.49,6944.53 ; USB2.13@3786.85,6668.75 3934.12,6816.02 4050,6816.02 4115,6881.02 H4.4 4005,6876.02 3690,6876.02 v2@3621.49,6944.53 ; v1@3805,6371.02 3810,6366.02 3810,6351.35 USB2.14@3786.85,6328.2 ; v1(3810,5506.02) 3910,5406.02 ; v1(3910,4671.02) v1(3910,4556.02) ; v1(4020,4846.02) 3990,4876.02 v1(3990,5116.02) 3975,5116.02 3935,5156.02 v1(3935,5331.02) ; v1(4090,6251.02) 3786.85,6251.02 ; v1(4210,4676.02) 4190,4676.02 4115,4601.02 4115,4531.02 4135,4511.02 4135,4491.02 4090,4446.02 v1(4035,4446.02) 4020,4446.02 v1(3910,4556.02) ; v1(4560,4996.02) 4590,4996.02 v1(4715,4871.02) 4810,4776.02 4810,4666.02 4855,4621.02 v1(4855,4611.02) ; v1(4900,5296.02) 4975,5371.02 v1(5040,5371.02) ; v1(4905,5616.02) 4940,5581.02 ; v1(5110,4611.02) v1(4855,4611.02) ; H5.5 H5.6 5810,6356.02 5810,6501.02 5910,6601.02 H1.5 v2@5990,6981.02 ; v2(6015,4081.02) 6015,4121.02 5685,4451.02 v1(5525,4451.02) ; v2(6015,7006.02) v2@5990,6981.02 ; v2@3621.49,6944.53 3621.49,6668.75 3621.49,6328.2 USB2.14@3786.85,6328.2 ; 3786.85,6251.02 USB2.14@3786.85,6328.2 ; 3786.85,6251.02 3786.85,6049.17 3875,5961.02 3875,5621.02 3910,5586.02 3910,5406.02 ; 3910,5406.02 3935,5381.02 v1(3935,5331.02) ; v1(3935,5331.02) 3965,5331.02 4020,5386.02 4100,5386.02 v1(4120,5406.02) 4250,5536.02 v1(4250,5596.02) 4455,5801.02 4455,5846.02 4505,5896.02 v1(4545,5896.02) 4545,6131.02 4435,6241.02 4435,6311.02 4534.99,6411.02 SW2.C ; SW2.C 4534.99,6446.02 4675,6586.02 5180,6586.02 U7.2 5885,6876.02 v2@5990,6981.02 ; SW2.C 4604.56,6361.02 4800,6361.02 4800,6191.02 4965,6026.02 5060,6026.02 5130,5956.02 5130,5826.02 5035,5731.02 5035,5601.02 5015,5581.02 4940,5581.02 ; v1(4855,4611.02) 4890,4576.02 v1(4890,4516.02) 4760,4386.02 4760,4146.02 v1(4740,4126.02) 4760,4106.02 v1(4840,4106.02) 5125,4106.02 5140,4121.02 v1(5180,4121.02) 5365,4121.02 5585,4341.02 5585,4391.02 v1(5525,4451.02) ; 4940,5581.02 4940,5471.02 v1(5040,5371.02) ; v1(5040,5371.02) 5130,5371.02 v1(5240,5481.02) 5270,5451.02 5270,5406.02 5335,5341.02 5585,5341.02 5675,5251.02 v1(5925,5251.02) 5965,5211.02 5965,5096.02 5915,5046.02 5825,5046.02 5800,5071.02 v1(5705,5071.02) 5675,5071.02 v1(5605,5001.02) 5620,4986.02 v1(5620,4856.02) v1(5620,4701.02) 5620,4676.02 5595,4651.02 5535,4651.02 5495,4611.02 5495,4481.02 v1(5525,4451.02)
  other v1: 3808.5,6372.49
OSCIN: C15.2 U1.5 U4.2 X1.1 | length 2489.2
  Top Layer w6: X1.1 v1(4580,6231.02) ; U4.2 4734.66,4655.12 C15.2 4760.99,4672.01 4805,4716.02 4805,4901.04 v1(4770,4936.04) ; v1(4950,5141.02) 4980.47,5171.49 U1.5 4975.1,5214.07 4975.1,5260.92 v1(4965,5271.02)
  Inner1 w6: v1(4580,6231.02) 4640,6171.02 4640,5955.19 4415,5730.19 4415,5566.02 4520,5461.02 4775.84,5461.02 4965,5271.86 v1(4965,5271.02) ; v1(4770,4936.04) 4794.98,4961.02 4794.98,5055.17 4845.85,5106.04 4915.02,5106.04 v1(4950,5141.02)
OSCOUT: C16.2 U1.6 U4.1 X1.2 | length 2489
  Top Layer w6: C16.2 4547.44,4703.46 ; v1(4585,4741.02) 4547.44,4703.46 ; v1(4645,6221.02) 4655,6231.02 X1.2 ; U4.1 4675.34,4575.56 4547.44,4703.46 ; v1(4950,5096.02) 4985.16,5096.02 5000.16,5111.02 U1.6 5000.16,5265.86 v1(5000,5266.02)
  Inner1 w6: v1(4585,4741.02) 4740,4741.02 4805,4806.02 4805,5051.02 4850,5096.02 v1(4950,5096.02) ; v1(4645,6221.02) 4645,6181.02 4794.98,6031.04 4794.98,5571.01 4765,5541.02 4765,5500.19 4927.08,5338.1 4997.92,5338.1 5040,5296.02 5040,5270.04 5035.98,5266.02 v1(5000,5266.02)
PA11: R8.2 R26.2 U1.32 | length 2136.1
  Top Layer w6: v1(4515,4576.02) 4565,4526.02 R26.2 ; v1(4860,5226.02) 4980.47,5346.49 U1.32 4980.47,5575.87 5025,5620.4 5025,5636.02 5075,5686.02 5075,5756.02 5120,5801.02 5505,5801.02 5560,5856.02 5560,5918.91 R8.2
  Inner1 w6: v1(4665,4771.02) 4685,4791.02 4685,5146.02 4765,5226.02 v1(4860,5226.02)
  VCC w6: v1(4515,4576.02) 4515,4621.02 v1(4665,4771.02)
PA12: R9.2 R10.2 R27.2 R28.2 U1.33 | length 2177.4
  Top Layer w6: R27.2 4180,5591.02 v1(4220,5551.02) ; v1(4325,5481.02) 4276.33,5432.35 R28.2 4631.96,5422.98 4780,5571.02 4840,5571.02 v1(4865,5546.02) ; v1(4920,5456.02) 4940,5456.02 4960,5476.02 4960,5542.55 U1.33 4960.79,5591.81 v1(4985,5616.02) 5030,5661.02 5030,5776.02 5090,5836.02 5218.22,5836.02 R9.2 ; v1(5230,5631.02) 5283.04,5684.06 R10.2
  Inner1 w6: v1(4865,5546.02) 4920,5491.02 v1(4920,5456.02) ; v1(4985,5616.02) 5215,5616.02 v1(5230,5631.02)
  VCC w6: v1(4220,5551.02) 4270,5501.02 4305,5501.02 v1(4325,5481.02)
PC13: R7.2 U1.2 | length 483
  Top Layer w6: R7.2 4575.34,5195.68 4635,5136.02 4881.27,5136.02 4921.42,5176.17 U1.2
PC14: C13.1 U1.27 X2.2 | length 1042.2
  Top Layer w6: U1.27 5078.9,5579.92 5090,5591.02 5350,5591.02 5440,5681.02 5715,5681.02 5750.36,5716.38 C13.1 5790,5717.05 5790,5766.02 5868.12,5844.14 X2.2
PC15: C14.1 U1.28 X2.1 | length 972.7
  Top Layer w6: U1.28 5059.21,5575.87 5089.36,5606.02 5337.94,5606.02 5433.43,5701.51 ; C14.1 5433.43,5701.51 ; X2.1 5767.72,5863.74 5605.49,5701.51 5433.43,5701.51
PWM: R23.2 SW3.2 U1.11 | length 2121.8
  Top Layer w6: v1(4935,5996.02) 5105,5996.02 v1(5185,6076.02) ; v1(4950,5836.02) 4950,5826.02 4995,5781.02 4995,5741.65 R23.2 4989.37,5726.25 4955,5691.88 4955,5681.02 v1(4970,5666.02) ; U1.11 5098.58,5176.17 5128.73,5146.02 5245,5146.02 5270,5171.02 v1(5270,5221.02) ; v1(5185,6246.02) 5250.51,6246.02 5360.51,6356.02 SW3.2
  Inner1 w6: v1(4935,5996.02) 4935,5956.02 4910,5931.02 4910,5876.02 v1(4950,5836.02) ; v1(4970,5666.02) 5240,5666.02 5270,5636.02 v1(5270,5221.02) ; v1(5185,6076.02) v1(5185,6246.02)
RESET: C1.2 R3.1 SW1.2 U1.7 | length 2386.8
  Top Layer w6: SW1.2 4162.48,5853.54 4470,5546.02 v1(4705,5546.02) ; v1(4995,5296.02) 5010,5296.02 5028.26,5277.76 5028.26,5269.28 5022.26,5263.28 5022.26,5211.12 U1.7 5019.84,5076.18 5045,5051.02 5045,4971.02 5095,4921.02 5275,4921.02 5406.65,5052.67 C1.2 5606.67,4917.81 R3.1
  Inner1 w6: v1(4705,5546.02) 4955,5296.02 v1(4995,5296.02)
RXD: H1.4 U1.30 | length 2046.1
  Top Layer w6: U1.30 5020,5543.5 5020,5576.03 5055,5611.03 5055,5631.02 5100,5676.02 5100,5746.02 5134.97,5780.99 5604.97,5780.99 v1(5610,5786.02) ; v1(5840,6476.02) 5840,6506.02 5870,6536.02 5955,6536.02 H1.4
  Inner1 w6: v1(5610,5786.02) 5860,5786.02 6015,5941.02 6015,6006.02 5915,6106.02 5915,6401.02 v1(5840,6476.02)
SCL: OLED1.18 R22.2 U1.21 | length 2821.8
  Top Layer w6: OLED1.18 4731.1,4273.07 4749.06,4291.02 v1(4795,4291.02) ; U1.21 5379.21,5425.23 5435,5481.02 5700,5481.02 5730,5451.02 5800.23,5451.02 ; v1(5635,5426.02) 5775.23,5426.02 5800.23,5451.02 ; R22.2 5860,5515.59 5860,5466.02 5845,5451.02 5800.23,5451.02
  Inner1 w6: v1(4795,4291.02) 4810,4306.02 4909.16,4306.02 5085.02,4481.87 5085.02,4836.87 5189.15,4941.01 5274.15,4941.01 5360.02,5026.87 5360.02,5376.02 5425.02,5441.02 5620,5441.02 v1(5635,5426.02)
SDA: OLED1.19 OLED1.20 R21.2 U1.22 | length 2172.4
  Top Layer w6: OLED1.20 OLED1.19 4703.54,4279.56 v1(4735,4311.02) ; U1.22 5273.9,5444.92 5395.55,5566.57 R21.2@5450.55,5566.57 ; v1(5350,5466.02) R21.2@5450.55,5566.57 ; R21.2 R21.2@5450.55,5566.57
  Inner1 w6: v1(4735,4311.02) 4745,4321.02 4910,4321.02 5075,4486.02 5075,4841.02 5185,4951.02 5270,4951.02 5350,5031.02 v1(5350,5466.02)
SWCLK: H4.3 U1.37 | length 2791.4
  Top Layer w6: H4.3 4015,6911.02 v1(4175,6751.02) ; v1(4805,5521.02) 4805.95,5521.02 U1.37
  Inner1 w6: v1(4175,6751.02) 4230,6806.02 4230,6996.02 4305,7071.02 4750,7071.02 4860,6961.02 4860,6161.02 4805,6106.02 v1(4805,5521.02)
SWDIO: H4.2 U1.34 | length 2654.9
  Top Layer w6: H4.2 3915,7036.02 3940,7061.02 v1(4225,7061.02) ; v1(4940,5621.02) 4940,5544.44 U1.34
  Inner1 w6: v1(4225,7061.02) 4245.02,7081.04 4754.15,7081.04 4870.02,6965.17 4870.02,6156.87 4815.02,6101.87 4815.02,5656.01 4850,5621.02 4870,5621.02 4900,5651.02 4925,5651.02 4940,5636.02 v1(4940,5621.02)
TXD: H1.3 U1.31 | length 1560.6
  Top Layer w6: U1.31 5000.16,5575.87 5040,5615.71 5040,5631.02 5085,5676.02 5085,5685.46 5085.02,5686.02 5085.02,5751.04 5124.98,5791.01 5534.98,5791.01 v1(5565,5821.02) ; v1(5855,6356.02) 5900,6401.02 H1.3
  Inner1 w6: v1(5565,5821.02) 5855,6111.02 v1(5855,6356.02)
VCC: C2.2 C9.1 C10.2 C11.2 C12.2 C20.2 C21.2 C30.2 C31.2 D1.1 H1.2 H4.1 H5.1 H5.2 LED1.1 LED2.1 OLED1.6 OLED1.9 OLED1.11 Q5.3 R3.2 R13.1 R14.2 R18.1 R20.2 R21.1 R22.1 R31.2 U1.9 U1.24 U1.36 U6.5 | length 15349.3
  Top Layer w6: U6.5 3825,5243.2 3825,5131.02 ; v1(3980,5286.02) 3825,5131.02 ; v1(4085,4571.02) 4085,4523.89 C21.2 4235.43,4521.02 R13.1 ; v1(4110,4641.02) 4102.52,4641.02 C20.2 ; v1(4120,5056.02) 4060.11,4996.13 C11.2 3985,4881.64 3985,4758.55 C20.2 ; v1(4255,5691.02) 4304.2,5641.82 C2.2 ; C10.2 4304.2,5090.95 C12.2 4288.32,5131.02 v1(4345,5131.02) ; Q5.3 4670.28,5691.02 v1(4675,5691.02) ; R18.1 4710.53,5261.02 v1(4765,5261.02) ; v1(4860,5591.02) 4901.73,5549.29 U1.36 ; LED1.1 4895,4994.67 v1(4895,4951.02) ; OLED1.11 4924.02,4148.96 4951.95,4121.02 5007.06,4121.02 ; R31.2 v1(5020,5903.66) ; OLED1.9 4979.13,4148.96 5007.06,4121.02 ; U1.9 5060,5209.49 5060,5261.02 5080,5281.02 v1(5080,5466.02) 5126.52,5466.02 5144.79,5484.29 U1.24 ; OLED1.6 5061.81,4137.83 5045,4121.02 ; v1(5115,5066.02) 5115,5019.67 LED2.1 LED2.1@5128.65,5006.02 ; v1(5145,4091.02) 5075,4091.02 5045,4121.02 ; v1(5190,4726.02) 5209.79,4706.23 C30.2 ; R20.2 5233.92,4811.02 v1(5275,4811.02) ; D1.1 5425,6171.02 H5.2 H5.1 ; C31.2 5450.63,4455.39 v1(5510,4396.02) ; v1(5490,5616.02) 5490,5615.61 R21.1 5587.31,5518.3 R22.1 5815,5481.85 v1(5815,5481.02) ; v1(5825,4856.02) 5847.58,4878.6 R3.2 5900.8,4971.02 v1(5980,4971.02) ; 3825,5131.02 R14.2 3825,5086.02 3675,4936.02 3675,4798.46 C9.1 3847.44,4626.02 4002.26,4626.02 C20.2 ; 5007.06,4121.02 5045,4121.02
  VCC w6: H4.1 4205,6596.02 4205,5841.02 4270,5776.02 4270,5706.02 v1(4255,5691.02) ; v1(3980,5286.02) 3980,5396.02 4065,5481.02 4065,5641.02 4115,5691.02 v1(4255,5691.02) ; v1(4085,4571.02) 4085,4616.02 v1(4110,4641.02) ; v1(4120,5056.02) 4270,5056.02 v1(4345,5131.02) 4440,5226.02 4730,5226.02 v1(4765,5261.02) 4780,5246.02 4780,5066.02 v1(4895,4951.02) 4915,4931.02 4995,4931.02 5010,4946.02 5010,5026.02 5070,5086.02 5140,5086.02 5145,5081.02 ; 4655,5566.02 4645,5576.02 4645,5631.02 4675,5661.02 v1(4675,5691.02) ; v1(5020,5903.66) 5072.64,5851.02 5085,5851.02 5115,5821.02 5115,5731.02 4840,5731.02 4760,5651.02 4710,5651.02 v1(4670,5611.02) 4685,5596.02 4685,5591.02 ; v1(5115,5066.02) 5130,5066.02 5145,5081.02 ; v1(5145,4091.02) 5225,4091.02 5305,4171.02 5305,4336.02 5174,4467.02 5174,4710.02 v1(5190,4726.02) 5205,4741.02 ; D1.1 5365,6062.44 5365,5861.02 5290,5786.02 5260,5786.02 5245,5771.02 5245,5686.02 5315,5616.02 v1(5490,5616.02) ; H5.2 5655,6401.02 5890,6401.02 H1.2 ; v1(5815,5481.02) 5980,5316.02 v1(5980,4971.02) ; v1(5825,4856.02) 5595,4626.02 5595,4481.02 v1(5510,4396.02) 5380,4396.02 5275,4501.02 5275,4596.02 5330,4651.02 5330,4696.02 5285,4741.02 5205,4741.02 ; v1(4255,5691.02) 4385,5561.02 4655,5561.02 4685,5591.02 ; 4685,5591.02 v1(4860,5591.02) 4955,5591.02 v1(5080,5466.02) 5080,5351.02 5110,5321.02 5110,5166.02 5170,5106.02 5145,5081.02 ; 5145,5081.02 5160,5066.02 5160,4926.02 v1(5275,4811.02) 5205,4741.02
VREF: R12.2 U1.48 | length 528.9
  Top Layer w6: v1(4770,4976.02) 4840,4906.02 4865,4906.02 4886.05,4884.97 R12.2 ; v1(4810,5191.02) 4810,5235.07 U1.48
  Inner1 w6: v1(4770,4976.02) 4770,5151.02 v1(4810,5191.02)
pads on no net: OLED1.7 SW2.6 SW2.7 SW2.D SW2.E U1.1 U1.3 U1.4 U1.12 U1.13 U1.14 U1.15 U1.18 U1.19 U1.25 U1.26 U1.29 U1.38 U1.39 U1.40 U1.41 U1.42 U1.43 U1.45 U1.46 USB1.6 USB1.7 USB1.8 USB1.9 USB2.3 USB2.9
copper on no net: | length 11490
  Top Layer w10: 3515,3975 6120,3975 6120,7115 3515,7115 3515,3975

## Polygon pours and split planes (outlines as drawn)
GND on Bottom Layer "Bottom Layer-GND" (solid, remove dead copper, pour order 0): 3000,3591.02 6420,3591.02 6420,7261.02 3000,7261.02
VCC on VCC "VCC-VCC" (solid, remove dead copper, pour order 1): 3215,3351.02 6780,3351.02 6780,7556.02 3215,7556.02
VCC on Top Layer "Top Layer-VCC" (solid, remove dead copper, pour order 2): 3325,3696.02 7420,3696.02 7420,7891.02 3325,7891.02

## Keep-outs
Board Outline Layer:
  lines w10: 3515,3976.02 6120,3976.02 6120,7111.02 3515,7111.02 3515,3976.02

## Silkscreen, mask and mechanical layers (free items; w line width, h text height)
Top Silkscreen Layer:
  text "VCC" at 3767.51,7056.01 h29.2
  text "SWCLK" at 3919.94,7056.01 h29.2
  text "GND" at 4087.51,7056.01 h29.2
  text "SWDIO" at 3859.94,6886.01 h29.2
  text "GND" at 5917.51,6555.68 h29.2 r90
  text "RXD" at 5915.01,6453.53 h29.2 r90
  text "TXD" at 6069.99,6453.51 h29.2 r270
  text "VCC" at 6064.99,6343.51 h29.2 r270
  text "5V" at 6064.99,6227.23 h29.2 r270
  text "木东出品" at 3770.49,4211.1 h135.94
